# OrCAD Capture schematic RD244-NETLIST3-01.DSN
size A3
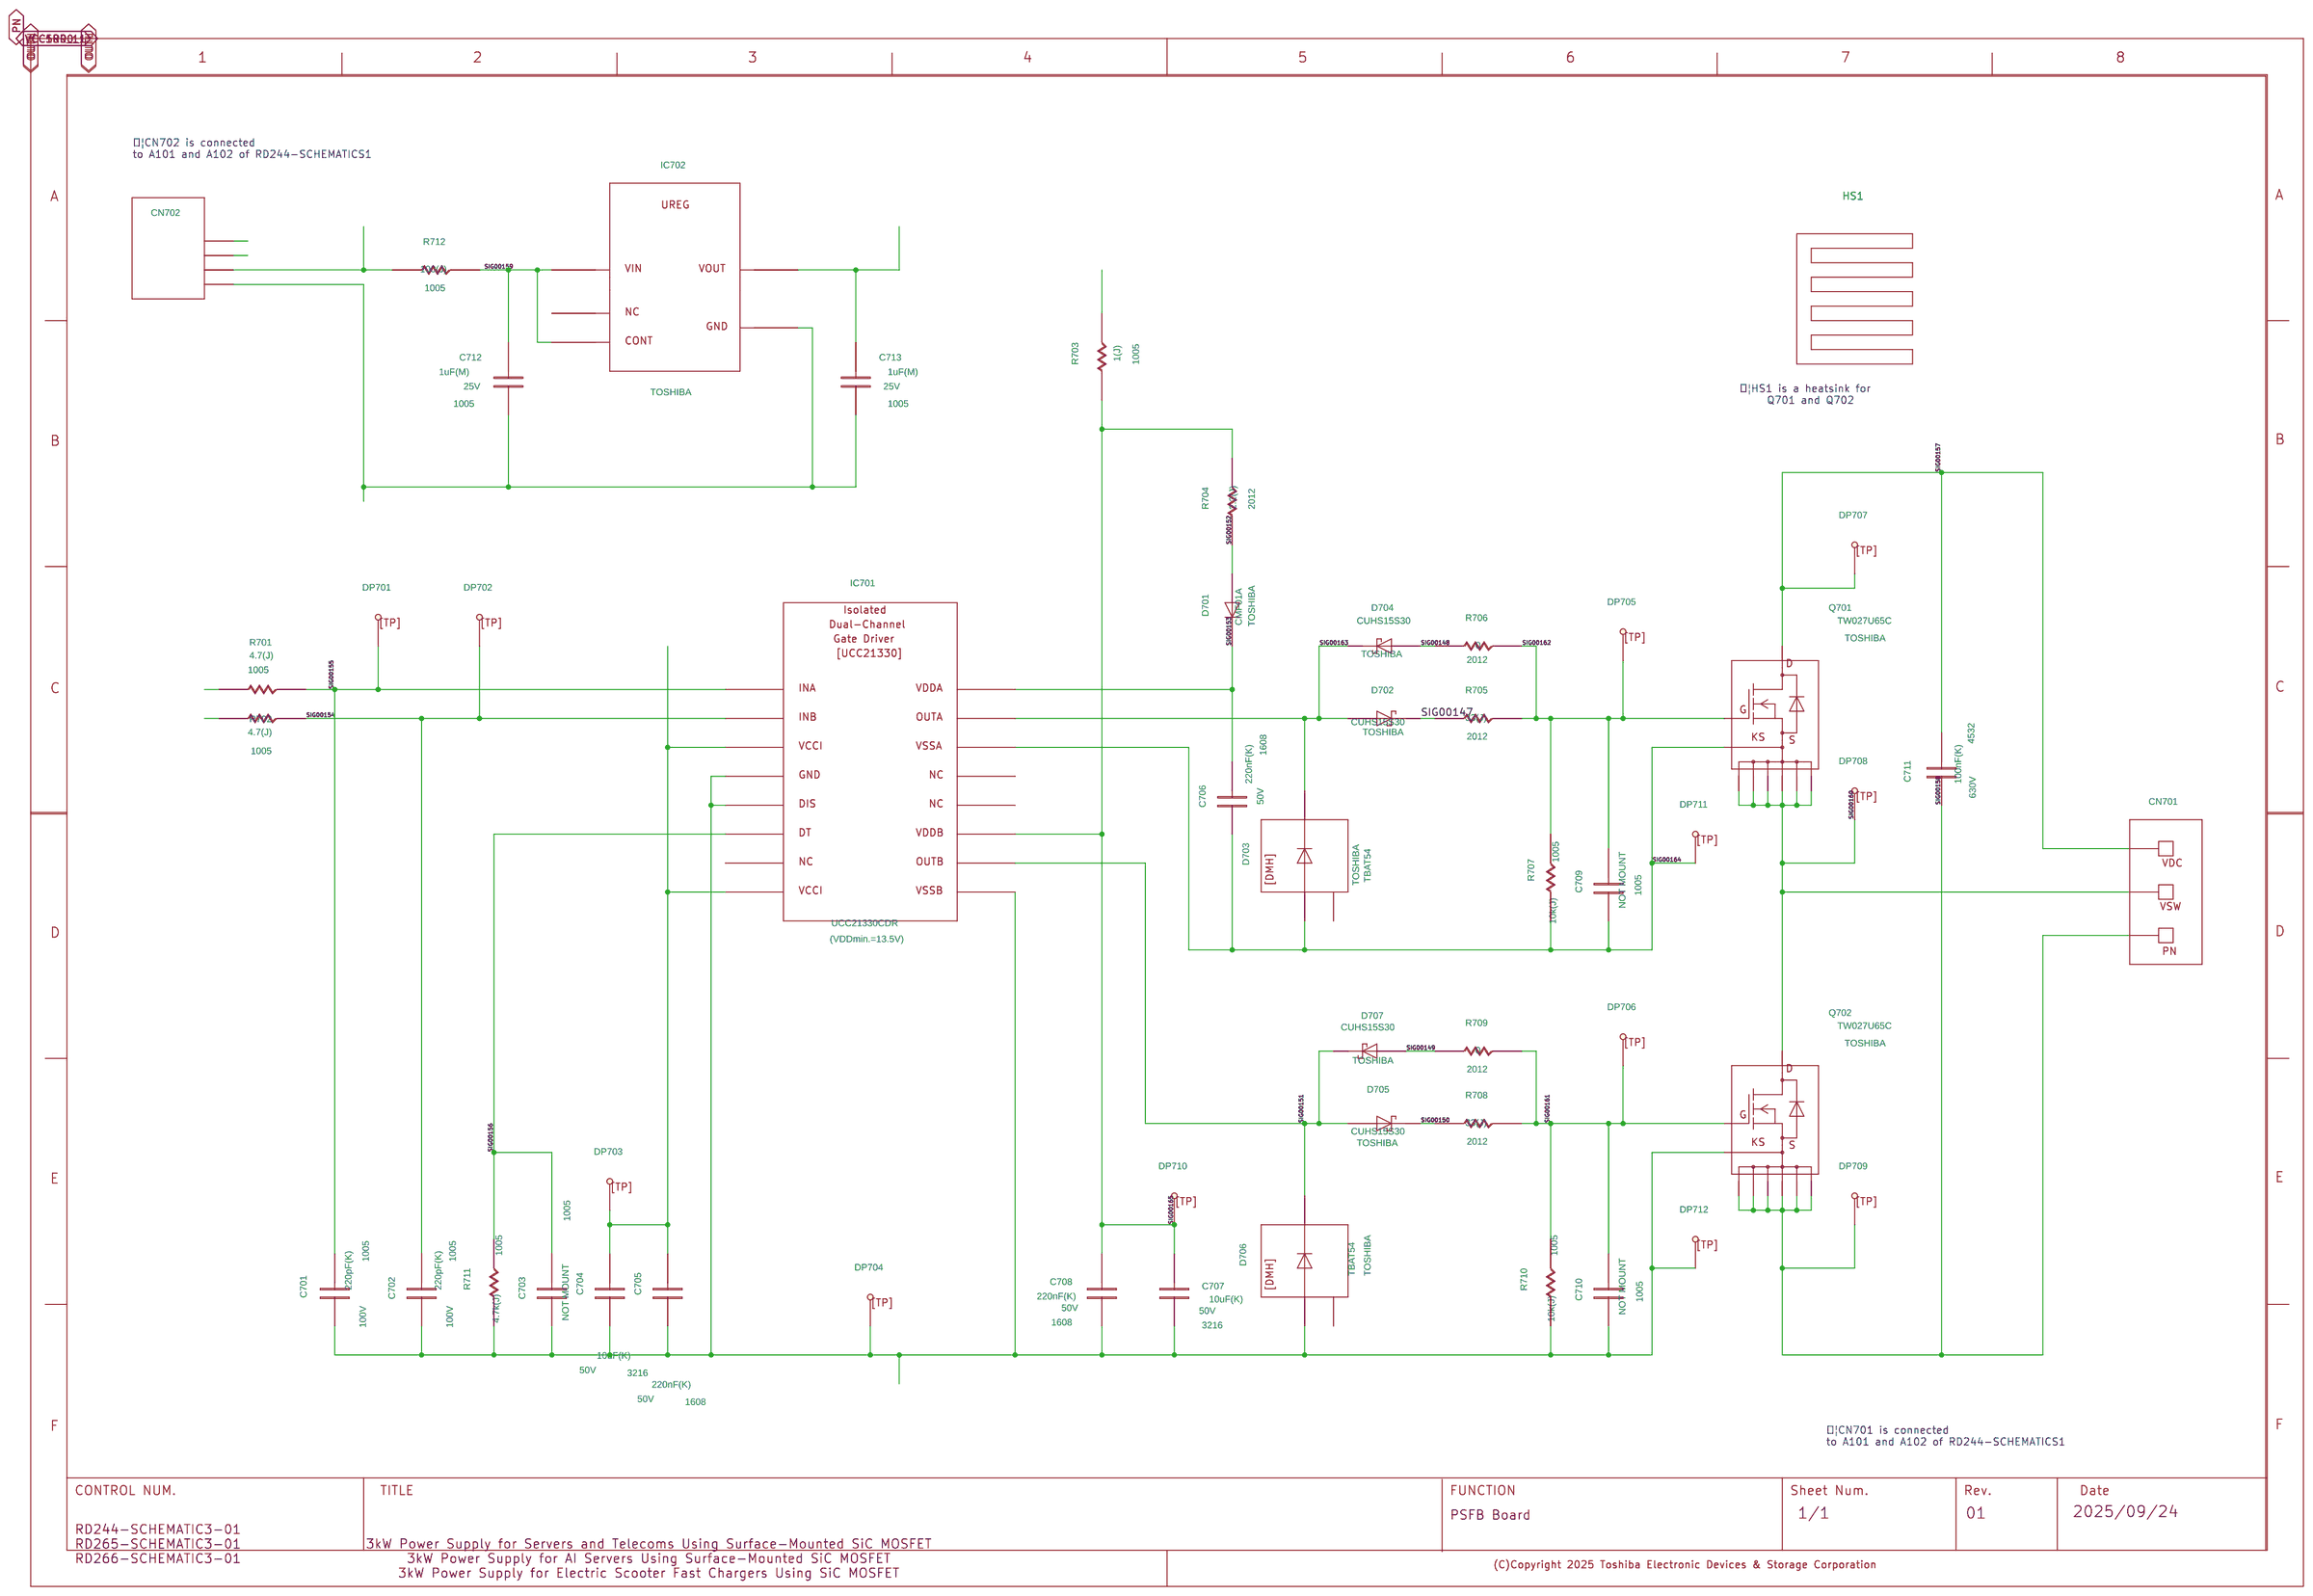
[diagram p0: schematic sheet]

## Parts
C701  C
C702  C
C703  C
C704  C
C705  C1608
C706  C1608
C707  C
C708  C1608
C709  C
C710  C
C711  C
C712  C
C713  C
CN701  RD-244_CN_FROM_FB
CN702  TSW-104-08-G-S-RA
D701  D
D702  CUHS15S30
D703  DMH
D704  CUHS15S30
D705  CUHS15S30
D706  DMH
D707  CUHS15S30
DP701  TP
DP702  TP
DP703  TP
DP704  TP
DP705  TP
DP706  TP
DP707  TP
DP708  TP
DP709  TP
DP710  TP
DP711  TP
DP712  TP
HS1  UB3040-6B
IC701  UCC21330
IC702  TCR1HF50B
Q701  NCHMOSFET_TOLL-02
Q702  NCHMOSFET_TOLL-02
R701  R
R702  R
R703  R
R704  R
R705  R
R706  R
R707  R
R708  R
R709  R
R710  R
R711  R
R712  R
U?#1  WAKU_DEF100

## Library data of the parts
C701 C702 = C: CHIPSIZE: 1005; COMP: PRT_52; COMPONENTTYPE: 4; GCOUNT: 1; MAXGCOUNT: 1; SAVECOUNT: 0; SIZECODESMD: 1005; VAL1: 220pF(K); VAL2: 100V; VAL3: GRM155R72A221KA01
C703 C709 C710 = C: CHIPSIZE: 1005; COMP: PRT_52; COMPONENTTYPE: 4; GCOUNT: 1; MAXGCOUNT: 1; NOTMOUNT: NOT MOUNT; SAVECOUNT: 0; SIZECODESMD: 1005; VAL1: 220pF(K); VAL2: 100V; VAL3: GRM155R72A221KA01
C704 C707 = C: CHIPSIZE: 3216; COMP: PRT_46; COMPONENTTYPE: 4; GCOUNT: 1; MAXGCOUNT: 1; SAVECOUNT: 0; SIZECODESMD: 3216; VAL1: 10uF(K); VAL2: 50V; VAL3: C3216X7R1H106K160AC
C705 C706 C708 = C1608: ADSCNVFLAG: ON; ADSCOMPONENTNAME: C_1005; CHIPSIZE: 1005; COMPONENTTYPE: 4; GCOUNT: 1; ICX_PART_MODEL: CON_220N; MAXGCOUNT: 1; SIZECODESMD: 1608; SQ_PART_MODEL: CON_220N; VAL1: 220nF(K); VAL2: 50V; VAL3: C1608X7R1H224K080AB
C711 = C: ADSCNVFLAG: ON; ADSCOMPONENTNAME: C_4532; COMP: GRJ43DR72J104KWJ1K; COMPONENTTYPE: 4; GCOUNT: 1; ICX_PART_MODEL: CON_100N; MAXGCOUNT: 1; SAVECOUNT: 0; SIZECODESMD: 4532; SQ_PART_MODEL: CON_100N; VAL1: 100nF(K); VAL2: 630V; VAL3: GRJ43DR72J104KWJ1K
C712 C713 = C: ADSCNVFLAG: ON; ADSCOMPONENTNAME: C_1608; CHIPSIZE: 1005; COMP: PRT_52; COMPONENTTYPE: 4; GCOUNT: 1; ICX_PART_MODEL: CON_1U; MAXGCOUNT: 1; SAVECOUNT: 0; SIZECODESMD: 1005; SQ_PART_MODEL: CON_1U; VAL1: 1uF(M); VAL2: 25V; VAL3: GRM155C81E105ME11
CN701 = RD-244_CN_FROM_FB: COMPONENTTYPE: 4
CN702 = TSW-104-08-G-S-RA: COMPONENTTYPE: 4
D701 = D: COMP: PRT_14; COMPONENTTYPE: 4; GCOUNT: 1; MAXGCOUNT: 1; USERCOMPTEXT2: 600V,2A; USERCOMPTEXT3: TOSHIBA; VAL3: CMF01A
D702 D704 D705 D707 = CUHS15S30: COMPONENTTYPE: 4; USERCOMPTEXT2: 30V,1.5A; USERCOMPTEXT3: TOSHIBA
D703 D706 = DMH: COMP: PRT_25; COMPONENTTYPE: 4; USERCOMPTEXT2: 30V,0.2A; USERCOMPTEXT3: TOSHIBA; VAL3: TBAT54
DP701-DP712 = TP: COMP: DTP815; COMPONENTTYPE: 4; USERCOMPTEXT1: ƒ³1.5mm
HS1 = UB3040-6B: COMPONENTTYPE: 4
IC701 = UCC21330: COMPONENTTYPE: 4; USERCOMPTEXT1: (VDDmin.=13.5V); VAL3: UCC21330CDR
IC702 = TCR1HF50B: COMPONENTTYPE: 4; SAVECOUNT: 17; USERCOMPTEXT3: TOSHIBA
Q701 Q702 = NCHMOSFET_TOLL-02: COMPONENTTYPE: 4; USERCOMPTEXT3: TOSHIBA; VAL3: TW027U65C
R701 R702 = R: CHIPSIZE: 1608; COMP: GDM010004481; COMPONENTTYPE: 4; GCOUNT: 1; MAXGCOUNT: 1; SAVECOUNT: 0; SIZECODESMD: 1005; VAL1: 4.7(J); VAL2: 63mW; VAL3: RK73B1ETTP4R7J
R703 = R: CHIPSIZE: 1608; COMP: GDM010004481; COMPONENTTYPE: 4; GCOUNT: 1; MAXGCOUNT: 1; SAVECOUNT: 0; SIZECODESMD: 1005; VAL1: 1(J); VAL2: 63mW; VAL3: RK73B1ETTP1R0J
R704 = R: CHIPSIZE: 3216; COMP: R2012; COMPONENTTYPE: 4; GCOUNT: 1; MAXGCOUNT: 1; SAVECOUNT: 0; SIZECODESMD: 2012; VAL1: 2.2(J); VAL2: 125mW; VAL3: SG732ATTD2R2K
R705 R708 = R: CHIPSIZE: 3216; COMP: R2012; COMPONENTTYPE: 4; GCOUNT: 1; MAXGCOUNT: 1; SAVECOUNT: 0; SIZECODESMD: 2012; VAL1: 33(J); VAL2: 500mW; VAL3: RK73B2ATTD330J
R706 R709 = R: CHIPSIZE: 3216; COMP: R2012; COMPONENTTYPE: 4; GCOUNT: 1; MAXGCOUNT: 1; SAVECOUNT: 0; SIZECODESMD: 2012; VAL1: 0; VAL2: 500mW; VAL3: RK73Z2ATTD
R707 R710 = R: CHIPSIZE: 1608; COMP: GDM010004481; COMPONENTTYPE: 4; GCOUNT: 1; MAXGCOUNT: 1; SAVECOUNT: 0; SIZECODESMD: 1005; VAL1: 10k(J); VAL2: 63mW; VAL3: RK73B1ETTP103J
R711 = R: CHIPSIZE: 1608; COMP: GDM010004481; COMPONENTTYPE: 4; GCOUNT: 1; MAXGCOUNT: 1; SAVECOUNT: 0; SIZECODESMD: 1005; VAL1: 4.7k(J); VAL2: 63mW; VAL3: RK73B1ETTP472J
R712 = R: CHIPSIZE: 1608; COMP: GDM010004481; COMPONENTTYPE: 4; GCOUNT: 1; MAXGCOUNT: 1; SAVECOUNT: 0; SIZECODESMD: 1005; VAL1: 100(J); VAL2: 63mW; VAL3: RK73B1ETTP101J
U?#1 = WAKU_DEF100: COMPONENTTYPE: 2; DATE: 2025/09/24; DESIGNED: TOSHIBA; DRAWINGNUMBER: RD244-SCHEMATIC3-01 / RD265-SCHEMATIC3-01 / RD266-SCHEMATIC3-01; FUNCTION: PSFB Board; PAGENUMBER: 1; REVISION: 01; SAVECOUNT: 5; SHEETNUMBER: 1/1; SHTSAVECOUNT: 149; TITLE: 3kW Power Supply for Servers and Telecoms Using Surface-Mounted SiC MOSFET / 3kW Power Supply for AI Servers Using Surface-Mounted SiC MOSFET / 3kW Power Supply for Electric Scooter Fast Chargers Using SiC MOSFET; UPDATEDATE: 2025.9.25; UPDATETIME: 14:02:38

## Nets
VCC5R0_1: C704.2 C705.2 C713.2 DP703.1 IC701.3 IC701.8 IC702.5
VCC18R0_1: CN702.3 R703.2 R712.1
OUTH: CN702.1 R701.1
OUTL: CN702.2 R702.1
PN: C701.1 C702.1 C703.1 C704.1 C705.1 C707.1 C708.1 C710.1 C712.1 C713.1 CN702.4 D706.A DP704.1 DP712.1 IC701.4 IC701.5 IC701.9 IC702.2 Q702.2 R710.1 R711.1
SIG00147: D702.C R705.1
SIG00148: D704.A R706.1
SIG00149: D707.A R709.1
SIG00150: D705.C R708.1
SIG00151: D705.A D706.C D707.C IC701.10
SIG00152: D701.A R704.1
SIG00153: C706.2 D701.C IC701.16
SIG00154: C702.2 DP702.1 IC701.2 R702.2
SIG00155: C701.2 DP701.1 IC701.1 R701.2
SIG00156: C703.2 IC701.6 R711.2
SIG00157: C711.2 CN701.1 DP707.1 Q701.9
SIG00158: C711.1 CN701.3 DP709.1 Q702.3 Q702.4 Q702.5 Q702.6 Q702.7 Q702.8
SIG00159: C712.2 IC702.1 IC702.3 R712.2
SIG00160: CN701.2 DP708.1 Q701.3 Q701.4 Q701.5 Q701.6 Q701.7 Q701.8 Q702.9
SIG00161: C710.2 DP706.1 Q702.1 R708.2 R709.2 R710.2
SIG00162: C709.2 DP705.1 Q701.1 R705.2 R706.2 R707.2
SIG00163: D702.A D703.C D704.C IC701.15
SIG00164: C706.1 C709.1 D703.A DP711.1 IC701.14 Q701.2 R707.1
SIG00165: C707.2 C708.2 DP710.1 IC701.11 R703.1 R704.2

Not connected (* = marked no-connect by the designer): D703 NC; D706 NC; IC701 7 12 13; IC702 4

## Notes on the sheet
- ¦CN702 is connected
  to A101 and A102 of RD244-SCHEMATICS1
- ¦HS1 is a heatsink for
       Q701 and Q702
- ¦CN701 is connected
  to A101 and A102 of RD244-SCHEMATICS1
